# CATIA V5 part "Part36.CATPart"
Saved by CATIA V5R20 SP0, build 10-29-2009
Part number: socket countersunk head screw_din_DIN 7991 - M8 x 20 --- 20N
Revision: ANY
Definition: UNKNOWN
Nomenclature: socket countersunk head screw_din_DIN 7991 - M8 x 20 --- 20N
Source: Unknown
Bounding box of the stored display mesh (mm): x 0 to 20, y -7.59 to 7.59, z -7.785 to 7.785
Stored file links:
  C:\Users\Utente\Desktop\IO LAVORO\3D X SITO CF\CUMSA\3D files GR\GR 465050-10\Part36.CATPart
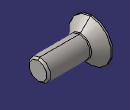
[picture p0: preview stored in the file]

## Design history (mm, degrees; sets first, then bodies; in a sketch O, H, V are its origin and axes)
Body1 "Hex" (main body)
  Solid1: solid without history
